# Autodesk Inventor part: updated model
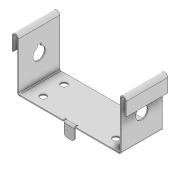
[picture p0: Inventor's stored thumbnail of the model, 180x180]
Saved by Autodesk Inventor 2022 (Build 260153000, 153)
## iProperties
Created: 2021-06
Part Number: updated model
Material: Generic
Document SubType Name: Sheet Metal
Designer: ASUS Laptop
Density: 1 g/cm^3
Flat Pattern Width: 5.12619 cm
Flat Pattern Length: 23.1855 cm
Flat Pattern Area: 118.853 cm^2
Sheet Metal Rule: Default_mm
Sheet Metal Width: 51.262 mm
Sheet Metal Length: 231.855 mm
Sheet Metal Area: 11885.332 mm^2
Appearance: Default
Author: ASUS Laptop
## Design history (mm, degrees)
node "Face1"
  sketch "Sketch2"
    geometry: L1 (0, 0)-(-100, 0); L2 (-100, 0)-(-100, -40); L3 (-100, -40)-(0, -40); L4 (0, -40)-(0, 0)
    constraints: 8 end point, 2 parallel, 1 horizontal, 1 perpendicular
    dimensions: "d0" = 40 distance of L3.end L1.start; "d1" = 100 distance of L2.end L3.end
sketch "Sketch3"
  geometry: L1 (0, 0)-(0, 40) reference; L2 (100, 0)-(0, 0) reference; 1 further point
  dimensions: "d3" = 15 distance from line of L1 point (15, 10); "d4" = 10 distance from line of L2 point (15, 10)
hole "Hole1" sketch "Sketch3" at (15, 10) diameter "d5" = 6; stored, may be unused: countersink angle "d9" = 90 deg, drill point angle "d11" = 118 deg; dims "d6" = 6, "d7" = 6, "d8" = 2, "d10" = 1 (= Thickness)
pattern_linear "Rectangular Pattern1" dims "d14" = 20, "d17" = 70
node "Flange1"
feature "Hem1" dims "d2" = 1 (= Thickness), "d28" = 1 (= BendReliefWidth), "d29" = 0.5 (= BendReliefDepth), "d30" = 2 (= MinimumRemnant), "d31" = 1 (= TransitionRadius), "d32" = 16, "d33" = 4, "d34" = 2 (= 0.5 x d33), "SeamGap" = 0.01
feature "Hem2" dims "d2" = 1 (= Thickness), "d35" = 1 (= BendReliefWidth), "d36" = 0.5 (= BendReliefDepth), "d37" = 2 (= MinimumRemnant), "d38" = 1 (= TransitionRadius), "d39" = 16, "d40" = 4, "d41" = 2 (= 0.5 x d40), "SeamGap" = 0.01
sketch "Sketch7"
  geometry: L1 (0, 0)-(40, 0) reference; L2 (40, 0)-(40, -48) reference; 2 further points
  dimensions: "d42" = 25 distance from line of point (20, -25) L1; "d43" = 20 distance from line of L2 point (20, -25)
feature "iFeature15:1" sketch "Sketch7"
sketch "Sketch8"
  geometry: L1 (40, 0)-(0, 0) reference; L2 (40, -48)-(40, 0) reference; 2 further points
  dimensions: "d50" = 25 distance from line of point (20, -25) L1; "d51" = 20 distance from line of point (20, -25) L2
feature "iFeature15:2" sketch "Sketch8"
node "Flange2"
feature "Corner Round1" dims "d69" = 3
body "Solid1"
face "Plate1" dims "d2" = 1 (= Thickness)
sketch "Sketch4"
  geometry: L1 through (0, -20) direction (-5.44e-32, 1); L2 through (-25, 0) direction (-1, -9.38e-32); L3 (-50, 0)-(-50, -40); L4 (-50, -40)-(0, -40)
  constraints: 6 end point, 1 horizontal, 1 perpendicular, 1 vertical
face "Plate2" dims "d2" = 1 (= Thickness), "d18" = 1 (= BendReliefWidth), "d19" = 0.5 (= BendReliefDepth), "d20" = 2 (= MinimumRemnant), "d21" = 1 (= TransitionRadius), "d22" = 50, "d23" = 90 deg, "d24" = 1 (= BendRadius), "d25" = 4 (= CornerReliefSize), "d26" = 1 (= GapSize), "d27" = 1 (= JacobiRadiusSize), "SeamGap" = 0.01
bend "Bend1" dims "d2" = 1 (= Thickness), "d18" = 1 (= BendReliefWidth), "d19" = 0.5 (= BendReliefDepth), "d20" = 2 (= MinimumRemnant), "d21" = 1 (= TransitionRadius), "d22" = 50, "d23" = 90 deg, "d24" = 1 (= BendRadius), "SeamGap" = 0.01
feature "Corner1" dims "d22" = 50, "d23" = 90 deg, "d25" = 4 (= CornerReliefSize), "d26" = 1 (= GapSize), "d27" = 1 (= JacobiRadiusSize)
sketch "Sketch9"
  geometry: L1 (-53, 0)-(-43, 0); L2 (-43, 0)-(-43, 13); L3 (-43, 13)-(-53, 13); L4 (-53, 13)-(-53, 0)
  constraints: 8 end point
face "Plate3" dims "d2" = 1 (= Thickness), "d58" = 1 (= BendReliefWidth), "d59" = 0.5 (= BendReliefDepth), "d60" = 2 (= MinimumRemnant), "d61" = 1 (= TransitionRadius), "d62" = 10, "d63" = 13, "d64" = 90 deg, "d65" = 1 (= BendRadius), "d66" = 4 (= CornerReliefSize), "d67" = 1 (= GapSize), "d68" = 1 (= JacobiRadiusSize), "SeamGap" = 0.01
bend "Bend2" dims "d2" = 1 (= Thickness), "d58" = 1 (= BendReliefWidth), "d59" = 0.5 (= BendReliefDepth), "d60" = 2 (= MinimumRemnant), "d61" = 1 (= TransitionRadius), "d63" = 13, "d64" = 90 deg, "d65" = 1 (= BendRadius), "SeamGap" = 0.01
feature "Corner2" dims "d63" = 13, "d64" = 90 deg, "d66" = 4 (= CornerReliefSize), "d67" = 1 (= GapSize), "d68" = 1 (= JacobiRadiusSize)
sketch "Sketch5"
  geometry: L1 (1, 0)-(0, 0); L2 (-4, 0)-(-4, -13); L3 (-4, -13)-(-5, -13); L4 (-5, -13)-(-5, 0); A1 r 2 centre (-2, 0) between (0, 0) and (-4, 0); A2 r 3 centre (-2, 0) between (1, 0) and (-5, 0)
  constraints: 8 end point, 4 point on circle
sketch "Sketch6"
  geometry: L1 (1, 0)-(0, 0); L2 (-4, 0)-(-4, -13); L3 (-4, -13)-(-5, -13); L4 (-5, -13)-(-5, 0); A1 r 2 centre (-2, 0) between (0, 0) and (-4, 0); A2 r 3 centre (-2, 0) between (1, 0) and (-5, 0)
  constraints: 8 end point, 4 point on circle
feature "Definition1"
other parameters: "Thickness" = 1 (derived), "BendRadius" = 1 (= Thickness), "BendReliefWidth" = 1 (= Thickness), "BendReliefDepth" = 0.5 (= 0.5 x Thickness), "CornerReliefSize" = 4 (= 4 x Thickness), "MinimumRemnant" = 2 (= 2 x Thickness), "TransitionRadius" = 1 (= BendRadius), "JacobiRadiusSize" = 1 (= BendRadius), "GapSize" = 1 (= Thickness), "d49" = 0, "d57" = 0, "BendRadius" = 1, "BendReliefDepth" = 0.5, "BendReliefWidth" = 1, "CornerReliefSize" = 4, "GapSize" = 1, "JacobiRadiusSize" = 1, "MinimumRemnant" = 2, "Thickness" = 1, "TransitionRadius" = 1
